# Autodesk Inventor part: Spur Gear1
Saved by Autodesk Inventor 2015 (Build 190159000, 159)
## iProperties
Created: 2014-06
Part Number: Spur Gear1
Material: Steel
Document SubType Name: Modeling
Designer: User
Categories: <?xml version="1.0" encoding="UTF-16"?> <MemberInstance><Categories><FamilyTemplate><FamilyTemplateParameter ValueType="xs:double" Id="1" ObjectReferenceKey="da
Density: 1 g/cm^3
Appearance: Steel
CustomPartVersion: 1
Author: User
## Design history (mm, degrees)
sketch "Sketch1"
  geometry: C1 r 7.579 at (0, 0)
  constraints: 1 centre point
  dimensions: "d0" = 15.1583 diameter of C1 (= da_da)
extrude "Extrusion1" new body sketch "Sketch1" distance "d1" = 6 (= da_b); taper "d2" = 0 deg
workplane "Work Plane2"
sketch "Sketch2"
  geometry: C1 r 7.579 at (0, 0) reference; C2 r 7 at (0, 0)
  constraints: 1 centre point, 1 coincident
  dimensions: "d3" = 14 diameter of C2 (= da_dw)
feature "Pitch Diameter" sketch "Sketch2" dims "d4" = 10, "d5" = 0
workplane "Work Plane8"
workplane "Work Plane9"
feature "Spur Gear" dims "da_b" = 6, "da_d" = 13.92, "da_aw" = 14, "da_da" = 15.1583, "da_df" = 12.5517, "da_dw" = 14, angle "da_beta" = 0 deg, "da_lefttooth" = 0, "da_righttooth" = 0
body "Solid1"
body "Srf1"
other parameters: "d16" = 14 (= da_aw), "d17" = 0, "d34" = 7.5 deg (computed from da_z), "d39" = 0, "d41" = 0, "d43" = 14 (= da_aw), "d46" = 14 (= da_aw), "d47" = 0, "d48" = 0
